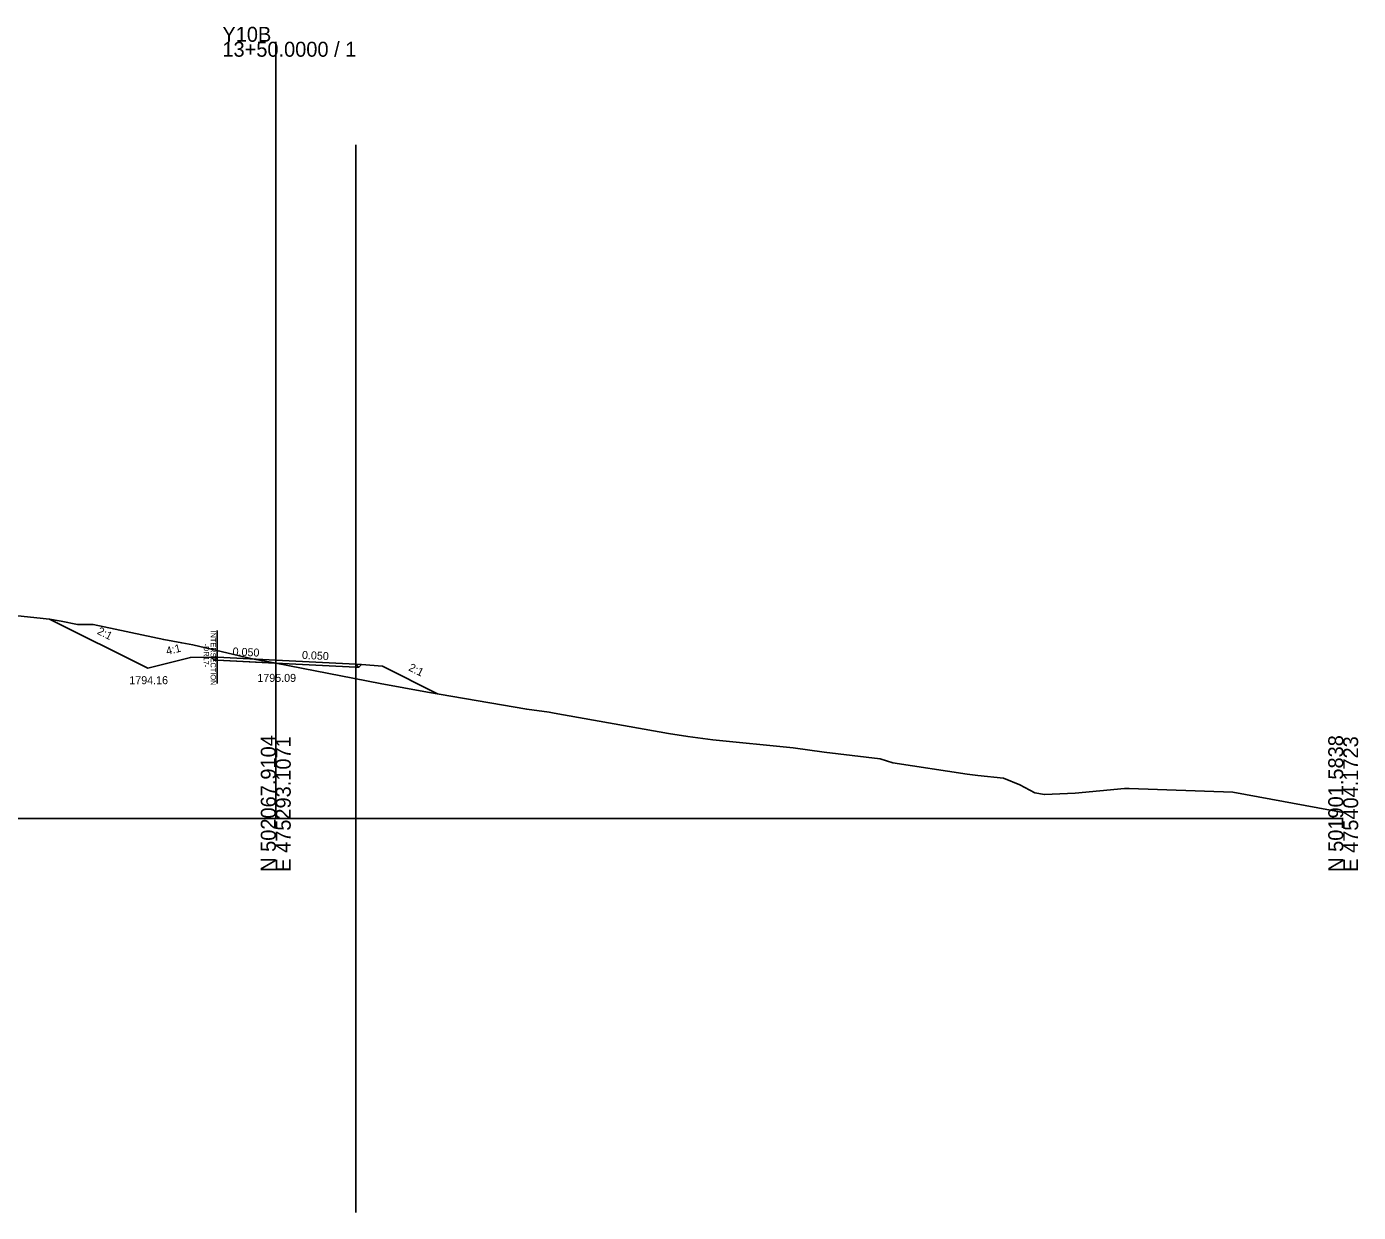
# Model space of a CAD drawing. Extents: x -26 to 1803, y -10 to 9558.
# Drawn here: x 153.3 to 402.8, y 3426.2 to 3648.4 of the extents above; entities that cross this region are included whole.
import ezdxf

# ---------------------------------------------------------------- set-up
doc = ezdxf.new("R2010")
doc.units = 0
for name, color, linetype in [('Exist Cross Section Cell', 7, 'Continuous'), ('Exist XS Center Line Elevation Label', 7, 'Continuous'), ('Exist XS Ground Line', 7, 'Continuous'), ('Prop XS Dump Level', 7, 'Continuous'), ('Prop XS Earthwork Shape', 7, 'Continuous'), ('Prop XS EOT Tick Mark', 7, 'Continuous'), ('Prop XS Finish Grade', 7, 'Continuous'), ('Prop XS Finish Grade Earthwork', 7, 'Continuous'), ('Prop XS Finish Grade Pavement', 7, 'Continuous'), ('Prop XS Hydro Fill Slope Data', 7, 'Continuous'), ('Prop XS Pvmt Edge Slope', 7, 'Continuous'), ('Prop XS SE Text', 7, 'Continuous'), ('Prop XS Shear Point Label', 7, 'Continuous'), ('Prop XS Shoulder Borrow Shape', 7, 'Continuous'), ('Prop XS Side Slope Text', 7, 'Continuous'), ('Prop XS Subgrade Earthwork', 7, 'Continuous'), ('Scratch_Level_0', 7, 'Continuous'), ('Scratch_Level_2', 7, 'Continuous')]:
    doc.layers.add(name, color=color, linetype=linetype)

msp = doc.modelspace()

# ---------------------------------------------------------------- linework, layer by layer
at = {"layer": 'Exist Cross Section Cell'}
for p, q in [((200, 3500), (200, 3645.53)), ((0, 3500), (200, 3500)), ((200, 3500), (400, 3500))]:
    msp.add_line(p, q, dxfattribs=at)
at = {"layer": 'Exist XS Ground Line'}
msp.add_lwpolyline([(147.42, 3538.39), (155.85, 3537.53), (157.53, 3537.37), (159.79, 3536.94), (162.86, 3536.36), (163.28, 3536.34), (165.76, 3536.33), (179.02, 3533.52), (182.39, 3532.89), (184.49, 3532.51), (195.3, 3530), (200, 3529.09), (219.56, 3525.31), (228.43, 3523.69), (247.03, 3520.45), (251.24, 3519.9), (252.14, 3519.73), (273.61, 3515.93), (277.2, 3515.38), (281.88, 3514.71), (296.91, 3513.22), (302.72, 3512.42), (313.22, 3511.17), (315.61, 3510.45), (329.57, 3508.29), (331.52, 3508.06), (336.35, 3507.54), (339.42, 3506.32), (342.23, 3504.81), (344.03, 3504.46), (349.79, 3504.71), (359.01, 3505.59), (359.89, 3505.63), (379.31, 3504.94), (400, 3501.09)], dxfattribs=at)
at = {"layer": 'Prop XS Dump Level'}
for p, q in [((189, 3530.21), (200, 3529.66)), ((200, 3529.66), (215, 3528.91))]:
    msp.add_line(p, q, dxfattribs=at)
at = {"layer": 'Prop XS Earthwork Shape'}
for points in [[(188.48, 3529.69), (187.98, 3530.2), (184, 3530.16), (176, 3528.16), (157.61, 3537.35), (159.79, 3536.94), (162.86, 3536.36), (163.28, 3536.34), (165.76, 3536.33), (179.02, 3533.52), (182.39, 3532.89), (184.49, 3532.51), (195.3, 3530), (199.84, 3529.12), (189, 3529.67)], [(199.84, 3529.12), (200, 3529.09), (219.56, 3525.31), (228.43, 3523.69), (230.28, 3523.37), (220, 3528.51), (216.06, 3528.82), (215.57, 3528.34), (215, 3528.37), (200, 3529.12)]]:
    msp.add_lwpolyline(points, close=True, dxfattribs=at)
at = {"layer": 'Prop XS EOT Tick Mark'}
for p, q in [((189, 3530.21), (189, 3531.21)), ((215, 3528.91), (215, 3529.91))]:
    msp.add_line(p, q, dxfattribs=at)
at = {"layer": 'Prop XS Finish Grade'}
msp.add_line((215, 3528.91), (216.06, 3528.82), dxfattribs=at)
at = {"layer": 'Prop XS Finish Grade Earthwork'}
for p, q in [((216.06, 3528.82), (220, 3528.51)), ((220, 3528.51), (230.28, 3523.37))]:
    msp.add_line(p, q, dxfattribs=at)
at = {"layer": 'Prop XS Finish Grade Pavement'}
for p, q in [((189, 3530.21), (200, 3529.66)), ((200, 3529.66), (215, 3528.91))]:
    msp.add_line(p, q, dxfattribs=at)
at = {"layer": 'Prop XS Hydro Fill Slope Data'}
msp.add_line((220, 3528.51), (230.28, 3523.37), dxfattribs=at)
at = {"layer": 'Prop XS Pvmt Edge Slope'}
msp.add_line((215, 3528.91), (215.57, 3528.34), dxfattribs=at)
at = {"layer": 'Prop XS Shear Point Label'}
msp.add_line((189, 3535.21), (189, 3525.26), dxfattribs=at)
at = {"layer": 'Prop XS Shoulder Borrow Shape'}
msp.add_lwpolyline([(215, 3528.91), (215.57, 3528.34), (216.06, 3528.82)], close=True, dxfattribs=at)
at = {"layer": 'Prop XS Subgrade Earthwork'}
for p, q in [((200, 3529.12), (189, 3529.67)), ((215, 3528.37), (200, 3529.12)), ((215, 3528.37), (215.57, 3528.34)), ((215.57, 3528.34), (216.06, 3528.82))]:
    msp.add_line(p, q, dxfattribs=at)
at = {"layer": 'Scratch_Level_0'}
for p, q in [((176, 3528.16), (157.61, 3537.35)), ((176, 3528.16), (157.61, 3537.35)), ((184, 3530.16), (176, 3528.16)), ((184, 3530.16), (176, 3528.16)), ((187.98, 3530.2), (184, 3530.16)), ((189, 3530.21), (187.98, 3530.2)), ((188.48, 3529.69), (187.98, 3530.2)), ((189, 3530.21), (188.48, 3529.69)), ((189, 3529.67), (188.48, 3529.69))]:
    msp.add_line(p, q, dxfattribs=at)
msp.add_lwpolyline([(189, 3530.21), (187.98, 3530.2), (188.48, 3529.69)], close=True, dxfattribs=at)
at = {"layer": 'Scratch_Level_2'}
msp.add_line((215, 3626.19), (215, 3426.19), dxfattribs=at)

# ---------------------------------------------------------------- texts
at = {"layer": 'Exist Cross Section Cell'}
for s, p in [('Y10B', (190, 3645.53)), ('13+50.0000 / 1', (190, 3642.73))]:
    msp.add_text(s, height=2.8, dxfattribs=at).set_placement(p)
for s, p in [('N 502067.9104', (200, 3490)), ('E 475293.1071', (202.8, 3490)), ('N 501901.5838', (400, 3490)), ('E 475404.1723', (402.8, 3490))]:
    msp.add_text(s, height=2.8, rotation=90, dxfattribs=at).set_placement(p)
at = {"layer": 'Exist XS Center Line Elevation Label'}
msp.add_text('1795.09', height=1.5, dxfattribs=at).set_placement((196.55, 3525.59))
at = {"layer": 'Prop XS Dump Level'}
for p in [(184, 3530.12), (220, 3528.47)]:
    msp.add_text('Case1', height=0.04, dxfattribs=at).set_placement(p)
at = {"layer": 'Prop XS SE Text'}
for p in [(191.88, 3530.56), (204.88, 3529.91)]:
    msp.add_text('0.050', height=1.5, rotation=357.1376, dxfattribs=at).set_placement(p)
at = {"layer": 'Prop XS Shear Point Label'}
for s, p in [('INTERSECTION', (187.79, 3535.21)), ('-DR17-', (186.49, 3532.78))]:
    msp.add_text(s, height=1, rotation=270, dxfattribs=at).set_placement(p)
at = {"layer": 'Prop XS Side Slope Text'}
msp.add_text('2:1', height=1.5, rotation=333.4349, dxfattribs=at).set_placement((224.75, 3527.81))
at = {"layer": 'Scratch_Level_0'}
for s, rotation, p in [('2:1', 333.4349, (166.41, 3534.63)), ('4:1', 14.0362, (179.64, 3530.61))]:
    msp.add_text(s, height=1.5, rotation=rotation, dxfattribs=at).set_placement(p)
msp.add_text('1794.16', height=1.5, dxfattribs=at).set_placement((172.56, 3525.16))

doc.saveas('drawing.dxf')
